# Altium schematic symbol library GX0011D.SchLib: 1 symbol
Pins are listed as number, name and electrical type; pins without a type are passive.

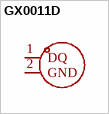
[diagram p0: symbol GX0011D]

## GX0011D
designator U?  (value not drawn)
footprint DFN-2L_L1.6-W0.8-P0.85-L
pins: 1 DQ, 2 GND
